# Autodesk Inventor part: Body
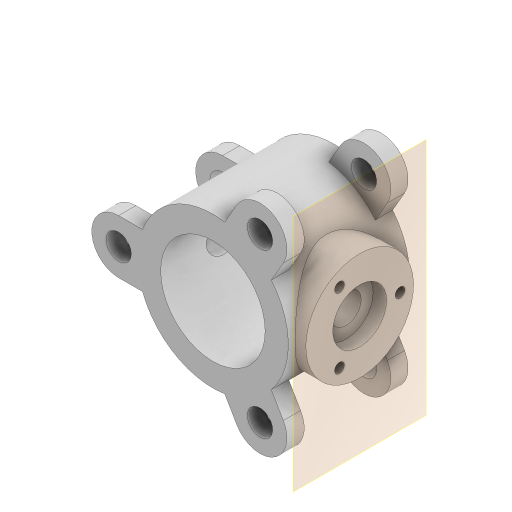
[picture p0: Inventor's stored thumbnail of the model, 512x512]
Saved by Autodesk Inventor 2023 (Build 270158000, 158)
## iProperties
Created: 2019-03
Part Number: Body
Material: Generic
Document SubType Name: Modeling
Designer: LENOVO-CADCIM
Density: 1 g/cm^3
Appearance: Default
Author: LENOVO-CADCIM
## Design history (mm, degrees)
sketch "Sketch1"
  geometry: C1 r 140 at (0, 0); C2 r 97 at (0, 0); 1 further point
  constraints: 2 centre point, 2 coincident
  dimensions: "d0" = 194 diameter of C2; "d1" = 280 diameter of C1
extrude "Extrusion1" new body sketch "Sketch1" stored distance "d2" = 225; taper "d3" = 0 deg
sketch "Sketch2"
  geometry: L1 (0, 0)-(-428, 0); L2 (-130.767, 50)-(-175, 50); L3 (-130.767, -50)-(-175, -50); C1 r 23.5 at (-175, 0); A1 r 175 centre (0, 0) between (-175, 0) and (-175, 0); A2 r 140 centre (0, 0) between (-130.767, 50) and (-130.767, -50) reference; A3 r 50 centre (-175, 0) between (-175, 50) and (-175, -50); 1 further point
  constraints: 6 end point, 6 point on circle, 3 centre point, 3 horizontal, 2 tangent, 1 coincident, 1 point on line, 1 other
  dimensions: "d4" = 350 diameter of A1; "d5" = 50 radius of A3; "d6" = 47 diameter of C1
extrude "Extrusion2" join sketch "Sketch2" distance "d7" = 32; taper "d8" = 0 deg
pattern_circular "Circular Pattern1" dims angle "d10" = 360 deg
mirror "Mirror1"
workplane "Work Plane1"
sketch "Sketch3"
  geometry: C1 r 100 at (0, 0); 1 further point
  constraints: 1 centre point, 1 coincident
  dimensions: "d13" = 200 diameter of C1
extrude "Extrusion3" join sketch "Sketch3" stored distance "d14" = 32; taper "d15" = 0 deg; dims "d4" = 350, "d5" = 50, "d6" = 47
sketch "Sketch4" dims "d16" = 150
  geometry: L1 (0, 0)-(102, 0); 2 further points
  constraints: 2 end point, 1 coincident, 1 horizontal, 1 horizontal alignment, 1 point on line, 2 other
hole "Hole1" sketch "Sketch4" at (75, 0) diameter "d17" = 18.376; stored, may be unused: countersink angle "d21" = 90 deg, drill point angle "d23" = 118 deg; dims "d18" = 40, "d19" = 4, "d20" = 2, "d22" = 47.3
pattern_circular "Circular Pattern2" dims angle "d25" = 360 deg
sketch "Sketch5"
  geometry: C1 r 100 at (0, 0) reference; 2 further points
  constraints: 1 coincident
hole "Hole2" sketch "Sketch5" at (0, 0) diameter "d27" = 56; stored, may be unused: countersink angle "d31" = 90 deg, drill point angle "d33" = 118 deg; dims "d28" = 6, "d29" = 100, "d30" = 25, "d32" = 310
body "Solid1"
